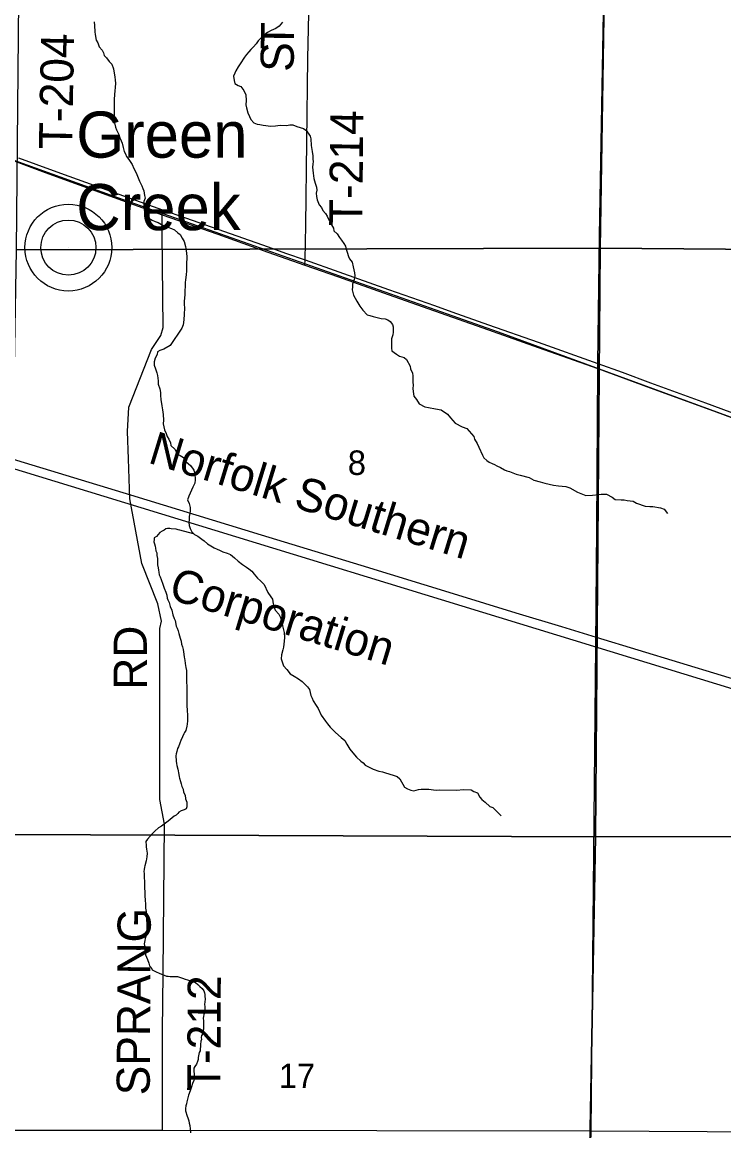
# Model space of a CAD drawing. Extents: x 36.7 to 70.7, y 0 to 22.
# Drawn here: x 42.275 to 43.478, y 17.404 to 19.304 of the extents above; entities that cross this region are included whole.
import ezdxf

# ---------------------------------------------------------------- set-up
doc = ezdxf.new("R2010")
doc.units = 0
for name, color, linetype in [('GM_X_County_Road', 7, 'Continuous'), ('GM_X_Minor_River', 7, 'Continuous'), ('GM_X_Rail_Line', 7, 'Continuous'), ('GM_X_Rail_Line_Text', 7, 'Continuous'), ('GM_X_Section', 7, 'Continuous'), ('GM_X_Section_Text', 7, 'Continuous'), ('GM_X_Township_Road', 7, 'Continuous'), ('GM_X_Township_Road_Text', 7, 'Continuous'), ('GM_X_Unincorporated', 7, 'Continuous'), ('GM_X_Unincorporated_Location', 7, 'Continuous'), ('GM_X_Unincorporated_Text', 7, 'Continuous'), ('GM_X_US_Route', 7, 'Continuous')]:
    doc.layers.add(name, color=color, linetype=linetype)

msp = doc.modelspace()

# ---------------------------------------------------------------- linework, layer by layer
at = {"layer": 'GM_X_County_Road'}
for points in [[(42.1609, 17.4056), (42.5156, 17.4053), (43.2502, 17.4045)], [(43.2502, 17.4045), (43.7467, 17.4014), (44.216, 17.4059), (44.498, 17.4024)]]:
    msp.add_lwpolyline(points, dxfattribs=at)
at = {"layer": 'GM_X_Minor_River'}
for points in [[(42.3988, 19.3045), (42.3991, 19.2985), (42.4001, 19.2871), (42.4005, 19.2829), (42.4023, 19.273), (42.4049, 19.2684), (42.4074, 19.2619), (42.4123, 19.2558), (42.4149, 19.2512), (42.4156, 19.247), (42.4197, 19.2428), (42.4242, 19.2367), (42.4291, 19.2321), (42.4317, 19.2241), (42.4331, 19.2165), (42.4342, 19.2104), (42.4349, 19.2047), (42.4352, 19.1994), (42.4347, 19.1918)], [(42.7216, 19.3041), (42.7155, 19.297), (42.7101, 19.2932), (42.7021, 19.2895), (42.696, 19.2862), (42.6907, 19.282), (42.6864, 19.2787), (42.6799, 19.2719), (42.6761, 19.2666), (42.6718, 19.2614), (42.6672, 19.2572), (42.6638, 19.2531), (42.6599, 19.2486), (42.6565, 19.2441), (42.6491, 19.2328), (42.6453, 19.2275), (42.6414, 19.2207), (42.6398, 19.2165), (42.6375, 19.2116), (42.6389, 19.204), (42.64, 19.1991), (42.6457, 19.1956), (42.6502, 19.1937), (42.6554, 19.1868), (42.6588, 19.1795), (42.6594, 19.17), (42.6589, 19.1621), (42.6596, 19.1571), (42.6618, 19.1487), (42.6648, 19.1423), (42.667, 19.1373), (42.6726, 19.1312), (42.6779, 19.1292), (42.6828, 19.1284), (42.6881, 19.1272), (42.7014, 19.1259), (42.7094, 19.1262), (42.7135, 19.1269), (42.7177, 19.1273), (42.7283, 19.1271), (42.734, 19.1282), (42.7394, 19.1282), (42.7461, 19.1251), (42.7575, 19.1215), (42.7631, 19.1177), (42.7654, 19.1135), (42.7687, 19.1085), (42.7702, 19.1043), (42.7708, 19.0929), (42.7722, 19.0826), (42.7736, 19.0747), (42.7736, 19.0693), (42.7739, 19.0652), (42.7735, 19.0606), (42.773, 19.0553), (42.7734, 19.0504), (42.7741, 19.045), (42.7751, 19.0359), (42.7773, 19.0279), (42.7795, 19.0211), (42.7802, 19.0161), (42.7794, 19.0112), (42.7797, 19.0055), (42.7811, 18.9998), (42.7844, 18.9907), (42.7882, 18.9864), (42.7904, 18.9815), (42.7949, 18.9761), (42.7979, 18.9715), (42.8005, 18.9666), (42.8034, 18.9605), (42.809, 18.9509), (42.8097, 18.9464), (42.8154, 18.941), (42.8191, 18.9352), (42.8224, 18.9303), (42.8266, 18.9249), (42.8292, 18.92), (42.8306, 18.915), (42.8321, 18.9097), (42.8343, 18.9024), (42.8361, 18.8982), (42.8406, 18.8925), (42.8428, 18.8845), (42.8449, 18.8746), (42.8456, 18.8693), (42.8441, 18.8632), (42.8413, 18.8553), (42.8413, 18.8504), (42.8408, 18.8454), (42.843, 18.8363), (42.8489, 18.826), (42.8542, 18.8172), (42.859, 18.8103), (42.8665, 18.8023)], [(42.4347, 19.1918), (42.4339, 19.1861), (42.4338, 19.18), (42.433, 19.1717), (42.4332, 19.1588), (42.433, 19.1391), (42.4336, 19.1315), (42.4351, 19.1242), (42.4369, 19.1193), (42.441, 19.1113), (42.4428, 19.1059), (42.4451, 19.1006), (42.4465, 19.0964), (42.4483, 19.0892), (42.4502, 19.0823), (42.4524, 19.0781), (42.4542, 19.0739), (42.4583, 19.0686), (42.4636, 19.0598), (42.4669, 19.0533), (42.4699, 19.0472), (42.4717, 19.043), (42.4743, 19.0373), (42.4765, 19.0315), (42.4806, 19.0235), (42.4824, 19.019), (42.4839, 19.0148), (42.4849, 19.0068), (42.486, 19.0026), (42.4841, 18.9969), (42.4836, 18.989), (42.4847, 18.9817), (42.4854, 18.9772), (42.4883, 18.9718), (42.4925, 18.9684), (42.4981, 18.9645), (42.503, 18.9622), (42.5083, 18.9606), (42.514, 18.9575), (42.5204, 18.9536), (42.5249, 18.9528), (42.5313, 18.9505), (42.5366, 18.9482), (42.5419, 18.9428), (42.546, 18.9401), (42.5494, 18.934), (42.5527, 18.9279), (42.5553, 18.9195), (42.5563, 18.9126), (42.5573, 18.9024), (42.5573, 18.8982), (42.5569, 18.8921), (42.5567, 18.8781), (42.5562, 18.8709), (42.5554, 18.8625), (42.5549, 18.858), (42.5545, 18.8504), (42.554, 18.8447), (42.5539, 18.8371), (42.5535, 18.8311), (42.5531, 18.8257), (42.553, 18.8208), (42.5533, 18.814), (42.5532, 18.8034), (42.5523, 18.7939), (42.5511, 18.7852), (42.5491, 18.7799)], [(42.8665, 18.8023), (42.871, 18.8011), (42.8767, 18.7999), (42.8813, 18.7983), (42.8858, 18.7971), (42.8903, 18.7963), (42.8972, 18.7959), (42.9021, 18.7939), (42.9062, 18.7908), (42.9099, 18.7859), (42.9114, 18.7817), (42.9109, 18.7726), (42.9105, 18.7684), (42.9085, 18.7616), (42.9083, 18.7456), (42.9087, 18.7411), (42.9169, 18.7349), (42.9222, 18.7318), (42.9298, 18.7295), (42.9339, 18.726), (42.9402, 18.7145), (42.9406, 18.71), (42.9443, 18.7024), (42.9446, 18.6978), (42.9448, 18.6872), (42.9452, 18.6818), (42.9451, 18.6765), (42.9454, 18.6712), (42.9468, 18.6632), (42.9513, 18.6575), (42.9558, 18.6498), (42.9656, 18.6448), (42.9717, 18.644), (42.9838, 18.6416), (42.9932, 18.6396), (43.0045, 18.6322), (43.0094, 18.6261), (43.0176, 18.6169), (43.0293, 18.6107), (43.0373, 18.6076), (43.0492, 18.5938), (43.0503, 18.5892), (43.0548, 18.582), (43.0581, 18.5759), (43.0644, 18.5618), (43.0666, 18.5576), (43.0715, 18.553), (43.0757, 18.5503), (43.0806, 18.5479), (43.0847, 18.546), (43.0889, 18.544), (43.0953, 18.5409), (43.1017, 18.5371), (43.1058, 18.5355), (43.1104, 18.5339), (43.1221, 18.5293), (43.1285, 18.528), (43.144, 18.5237), (43.1519, 18.5194), (43.1633, 18.5163), (43.1708, 18.5143), (43.186, 18.5107), (43.1943, 18.5095), (43.2068, 18.5086), (43.2136, 18.5059), (43.2272, 18.4989), (43.2415, 18.4931), (43.2529, 18.4933), (43.2636, 18.4947), (43.2677, 18.4954), (43.2765, 18.4953), (43.2866, 18.4903), (43.2915, 18.4861), (43.3021, 18.4856), (43.3071, 18.4855), (43.3124, 18.4843), (43.3226, 18.4834), (43.3283, 18.48), (43.343, 18.4749), (43.351, 18.4744), (43.3563, 18.4744), (43.3695, 18.4716), (43.3756, 18.4696), (43.3815, 18.4619)], [(42.5491, 18.7799), (42.5287, 18.7497), (42.518, 18.7438), (42.5115, 18.7412), (42.5073, 18.7393), (42.5065, 18.7348), (42.503, 18.7284), (42.5018, 18.7219), (42.5017, 18.7162), (42.5039, 18.7101), (42.5061, 18.7029), (42.5072, 18.6987), (42.5083, 18.6892), (42.5086, 18.6835), (42.5111, 18.6755), (42.5122, 18.6694), (42.5125, 18.6641), (42.5132, 18.6576), (42.5146, 18.6466), (42.516, 18.6398), (42.5171, 18.6318), (42.5173, 18.6219), (42.5169, 18.6159), (42.518, 18.6109), (42.519, 18.6052), (42.5224, 18.5991), (42.5239, 18.5941), (42.5265, 18.5896), (42.5298, 18.5831), (42.5301, 18.5785), (42.5369, 18.5724), (42.5417, 18.564), (42.5462, 18.5613), (42.5519, 18.5582), (42.556, 18.5513), (42.5646, 18.544), (42.5695, 18.5363), (42.5713, 18.5314), (42.5719, 18.5196), (42.5711, 18.5139), (42.5676, 18.5075), (42.561, 18.492), (42.5586, 18.4856), (42.5616, 18.4795), (42.563, 18.4723), (42.563, 18.4669), (42.5626, 18.462), (42.5617, 18.4571), (42.5613, 18.4518), (42.5612, 18.4465), (42.5616, 18.4415), (42.5634, 18.4362), (42.566, 18.4309), (42.5705, 18.4259), (42.5765, 18.4231), (42.5833, 18.4181), (42.5874, 18.4151), (42.5927, 18.4104), (42.5987, 18.4066), (42.6044, 18.4035), (42.6093, 18.4012), (42.6134, 18.3992), (42.6195, 18.3965), (42.6266, 18.3941), (42.6323, 18.3918), (42.6394, 18.3864), (42.6455, 18.3807), (42.653, 18.3745), (42.6597, 18.3703), (42.6639, 18.3676), (42.6688, 18.3633), (42.6729, 18.358), (42.6785, 18.3515), (42.6838, 18.3465), (42.6901, 18.3403), (42.6964, 18.3266), (42.7013, 18.3193), (42.7043, 18.3151), (42.7053, 18.3075), (42.7068, 18.3026), (42.709, 18.2965), (42.7153, 18.2899), (42.7183, 18.2838), (42.7201, 18.2774), (42.7216, 18.2694), (42.7241, 18.2583), (42.7248, 18.2496), (42.7243, 18.2432), (42.723, 18.2329), (42.7219, 18.2288), (42.7199, 18.2201), (42.7194, 18.2129), (42.7231, 18.201), (42.7287, 18.1949), (42.7347, 18.1876), (42.7414, 18.1834), (42.749, 18.1791), (42.755, 18.1745), (42.7644, 18.1653), (42.7677, 18.1607), (42.7703, 18.1504)], [(42.5692, 18.4273), (42.5455, 18.4336), (42.5429, 18.4344), (42.5391, 18.4352), (42.5308, 18.4361), (42.5282, 18.4366), (42.5244, 18.4366), (42.5217, 18.4359), (42.5186, 18.4333), (42.5152, 18.4319), (42.5113, 18.4293), (42.5086, 18.4263), (42.5055, 18.423), (42.5017, 18.4204), (42.5013, 18.4178), (42.5012, 18.4136), (42.5022, 18.4101), (42.5033, 18.4063), (42.504, 18.4025), (42.5046, 18.398), (42.5061, 18.3949), (42.5064, 18.39), (42.507, 18.385), (42.507, 18.3824), (42.5072, 18.377), (42.5075, 18.374), (42.5082, 18.3691), (42.5089, 18.3649), (42.5096, 18.3614), (42.5102, 18.3573), (42.5117, 18.3538), (42.5135, 18.3492), (42.5163, 18.3408), (42.5185, 18.3343), (42.5213, 18.3271), (42.5231, 18.3221), (42.5241, 18.3168), (42.5252, 18.3141), (42.5274, 18.3095), (42.5292, 18.303), (42.5317, 18.2965), (42.5334, 18.2885), (42.5359, 18.2824), (42.5374, 18.2786), (42.5394, 18.2691), (42.5409, 18.2656), (42.5427, 18.261), (42.5437, 18.2565), (42.5451, 18.2523), (42.5462, 18.2484), (42.5476, 18.2435), (42.5486, 18.2385), (42.55, 18.2336), (42.5511, 18.229), (42.5518, 18.2252), (42.5531, 18.2168), (42.5534, 18.2134), (42.5541, 18.2107), (42.5548, 18.2054), (42.5561, 18.1982), (42.5572, 18.1932), (42.5569, 18.1803), (42.5571, 18.1724), (42.5574, 18.167), (42.5573, 18.1617), (42.5575, 18.1572), (42.5578, 18.1496), (42.5576, 18.1443), (42.5578, 18.134), (42.5577, 18.1302), (42.5581, 18.1276), (42.5585, 18.1139), (42.5585, 18.1105), (42.5588, 18.1067), (42.5583, 18.1014), (42.5578, 18.0976), (42.5558, 18.0901), (42.5534, 18.0871), (42.5522, 18.0845), (42.5502, 18.0792), (42.5471, 18.0732), (42.5455, 18.0687), (42.5431, 18.0626), (42.5415, 18.0593), (42.5402, 18.0544), (42.539, 18.0502), (42.5386, 18.0472), (42.5389, 18.0438), (42.5392, 18.0411), (42.5395, 18.0377), (42.5398, 18.0339), (42.5405, 18.0301), (42.5419, 18.024), (42.5436, 18.0152), (42.5446, 18.011), (42.545, 18.0084), (42.5467, 18.003), (42.5478, 17.9988), (42.5488, 17.9943), (42.551, 17.99), (42.552, 17.9847)], [(42.7703, 18.1504), (42.7725, 18.1459), (42.7743, 18.1409), (42.7792, 18.1329), (42.7825, 18.1283), (42.7877, 18.1165), (42.7952, 18.1065), (42.7985, 18.1015), (42.803, 18.0958), (42.8124, 18.087), (42.8218, 18.0785), (42.8282, 18.0731), (42.8319, 18.067), (42.8367, 18.0582), (42.842, 18.0521), (42.8483, 18.0448), (42.8555, 18.0379), (42.8596, 18.0352), (42.863, 18.031), (42.8713, 18.0268), (42.8769, 18.024), (42.8868, 18.0209), (42.8928, 18.0197), (42.8981, 18.0177), (42.9113, 18.0138), (42.9178, 18.0118), (42.9223, 18.0076), (42.9304, 17.9935), (42.9357, 17.9904), (42.9414, 17.988), (42.9463, 17.9869), (42.9547, 17.989), (42.9589, 17.9898), (42.968, 17.9897), (42.9721, 17.99), (42.9805, 17.9888), (42.985, 17.9883), (42.9911, 17.9887), (43.0191, 17.9883), (43.0324, 17.9893), (43.0446, 17.9885), (43.0495, 17.9857), (43.0559, 17.9834), (43.0596, 17.9761), (43.0633, 17.9719), (43.0686, 17.9673), (43.0765, 17.9604), (43.0822, 17.9584), (43.0919, 17.9485), (43.0964, 17.9442)], [(42.552, 17.9847), (42.5546, 17.9793), (42.5552, 17.9733), (42.5563, 17.9706), (42.5574, 17.9675), (42.5573, 17.9641), (42.5576, 17.9596), (42.5564, 17.9562), (42.5529, 17.9544), (42.5476, 17.9529), (42.5438, 17.9507), (42.5422, 17.9481), (42.5395, 17.9455), (42.536, 17.9433), (42.5253, 17.9352), (42.5187, 17.9296), (42.5141, 17.9263), (42.5087, 17.9234), (42.5029, 17.9178), (42.4991, 17.9145), (42.4902, 17.9044), (42.4874, 17.8999), (42.4877, 17.8934), (42.488, 17.8908), (42.4887, 17.887), (42.4893, 17.8801), (42.4892, 17.8737), (42.4887, 17.8703), (42.4879, 17.8669), (42.4858, 17.8586), (42.485, 17.8559), (42.4842, 17.8522), (42.4841, 17.8488), (42.4844, 17.8453), (42.4846, 17.8385), (42.4852, 17.8317), (42.485, 17.8222), (42.4856, 17.8123), (42.4854, 17.8051), (42.4861, 17.8013), (42.4867, 17.7911), (42.4869, 17.7861), (42.4876, 17.7804), (42.4882, 17.7747), (42.4885, 17.7694), (42.4884, 17.7648), (42.4891, 17.7603), (42.4888, 17.7478), (42.4879, 17.7398), (42.4874, 17.7372), (42.4862, 17.7338), (42.4854, 17.7304), (42.4845, 17.7251), (42.4849, 17.7221), (42.4848, 17.7183), (42.4855, 17.7156), (42.4858, 17.7122), (42.4865, 17.7088), (42.4868, 17.7057), (42.4882, 17.7019), (42.49, 17.6981), (42.4922, 17.6919), (42.4936, 17.687), (42.4962, 17.6843), (42.498, 17.6805), (42.5006, 17.6789), (42.504, 17.6777), (42.5115, 17.6741), (42.516, 17.6721), (42.5186, 17.6713), (42.5228, 17.6697), (42.5258, 17.6693), (42.5292, 17.6688), (42.5322, 17.6688), (42.5352, 17.6691), (42.5417, 17.669), (42.5469, 17.6673), (42.5499, 17.6658), (42.5544, 17.6645), (42.5586, 17.6633), (42.5623, 17.6621), (42.5725, 17.6585), (42.5762, 17.655), (42.5799, 17.6515), (42.5836, 17.6484), (42.5866, 17.6442), (42.588, 17.6411), (42.5883, 17.6381), (42.5886, 17.6339), (42.589, 17.6312), (42.5881, 17.6244), (42.588, 17.6218), (42.5883, 17.6164), (42.5882, 17.6134), (42.5878, 17.61), (42.5877, 17.607), (42.5869, 17.6036), (42.586, 17.6006), (42.5856, 17.5972), (42.5859, 17.593), (42.5862, 17.5899)], [(42.5862, 17.5899), (42.586, 17.5805), (42.5847, 17.5706), (42.5827, 17.5676), (42.5823, 17.5642), (42.5826, 17.5608), (42.5818, 17.5582), (42.5809, 17.5525), (42.5806, 17.5415), (42.5787, 17.5389), (42.5774, 17.5328), (42.577, 17.5298), (42.5769, 17.5268), (42.5761, 17.5234), (42.5741, 17.5189), (42.571, 17.5148), (42.5694, 17.5118), (42.5694, 17.5087), (42.5697, 17.5053), (42.57, 17.5026), (42.5702, 17.4966), (42.5702, 17.4932), (42.5694, 17.4905), (42.5674, 17.4856), (42.5657, 17.4796), (42.5633, 17.4728), (42.5605, 17.4653), (42.5576, 17.4543), (42.5568, 17.4509), (42.556, 17.4472), (42.5551, 17.4426), (42.5554, 17.4388), (42.5583, 17.4297), (42.5593, 17.4266), (42.5607, 17.4217), (42.5618, 17.4178), (42.5625, 17.4133), (42.5631, 17.4076), (42.5637, 17.4011)]]:
    msp.add_lwpolyline(points, dxfattribs=at)
at = {"layer": 'GM_X_Rail_Line'}
for points in [[(39.9505, 19.9142), (40.2796, 19.7934), (40.742, 19.6245), (41.298, 19.4193), (41.8828, 19.2032), (42.4402, 19.0032), (43.0913, 18.7734), (43.6618, 18.5644), (44.5563, 18.22), (44.9526, 18.0665), (45.405, 17.9057), (45.5934, 17.8393)], [(39.4351, 19.5275), (39.5072, 19.4857), (39.6526, 19.4084), (39.8435, 19.3143), (39.9823, 19.2538), (40.1053, 19.2054), (40.2394, 19.1588), (40.707, 19.0117), (41.5752, 18.749), (42.4154, 18.492), (43.2547, 18.2349), (44.5058, 17.8517), (44.9515, 17.7199), (45.506, 17.5551), (45.5934, 17.5283)], [(42.2523, 18.5576), (42.4612, 18.4939), (42.6848, 18.4257), (42.8556, 18.3736), (43.0138, 18.3251), (43.1215, 18.2922), (43.1997, 18.2684), (43.259, 18.2503), (43.7587, 18.0984)]]:
    msp.add_lwpolyline(points, dxfattribs=at)
at = {"layer": 'GM_X_Section'}
for points in [[(44.2753, 19.8692), (44.2682, 18.9088), (43.2658, 18.9165), (43.2807, 19.8534), (43.3171, 19.855)], [(43.2807, 19.8534), (43.2658, 18.9165), (42.2659, 18.914), (42.2743, 19.8312), (42.3088, 19.8313)], [(43.2658, 18.9165), (43.2576, 17.9081), (42.2487, 17.912), (42.2659, 18.914)], [(44.2682, 18.9088), (44.2567, 17.9094), (43.2576, 17.9081), (43.2658, 18.9165)], [(43.2576, 17.9081), (43.2397, 16.908), (42.2388, 16.9146), (42.2487, 17.912)], [(44.2567, 17.9094), (44.2493, 16.9097), (43.2397, 16.908), (43.2576, 17.9081)]]:
    msp.add_lwpolyline(points, close=True, dxfattribs=at)
at = {"layer": 'GM_X_Township_Road'}
for p, q in [((43.2502, 17.4045), (43.2582, 18.2354)), ((43.2265, 16.2915), (43.2502, 17.4045))]:
    msp.add_line(p, q, dxfattribs=at)
for points in [[(42.76, 18.8877), (42.7602, 18.8965), (42.7612, 18.9559), (42.765, 19.2416), (42.7688, 19.4225)], [(43.2619, 18.7104), (43.262, 18.7192), (43.2645, 18.9386), (43.2731, 19.4156)], [(42.5153, 18.9641), (42.5155, 18.9741), (42.5157, 18.9826)], [(42.4601, 18.4872), (42.4574, 18.5556), (42.4559, 18.6027), (42.4581, 18.6444), (42.4969, 18.7433), (42.5128, 18.767), (42.5169, 18.7806), (42.515, 18.9412), (42.5153, 18.9641)], [(43.2582, 18.2354), (43.2601, 18.4382), (43.2619, 18.7104)], [(42.5169, 17.6753), (42.5191, 17.9298), (42.511, 17.9724), (42.5112, 18.2653), (42.5144, 18.2778), (42.5077, 18.3075), (42.4807, 18.3763), (42.4601, 18.4872)], [(42.5156, 17.4053), (42.516, 17.5758), (42.5169, 17.6733), (42.5169, 17.6753)]]:
    msp.add_lwpolyline(points, dxfattribs=at)
at = {"layer": 'GM_X_Unincorporated'}
for radius in [0.0744, 0.0472]:
    msp.add_circle((42.3545, 18.9177), radius, dxfattribs=at)
at = {"layer": 'GM_X_Unincorporated_Location'}
msp.add_line((42.3545, 18.9177), (42.3545, 18.9177), dxfattribs=at)
at = {"layer": 'GM_X_US_Route'}
for points in [[(42.0511, 19.1417), (42.0769, 19.1324), (42.212, 19.0834), (42.2689, 19.0633), (42.3145, 19.0466)], [(42.2689, 19.0716), (42.2986, 19.0608), (42.3411, 19.0455), (42.4267, 19.0145), (42.4694, 18.999), (42.5157, 18.9826), (42.555, 18.9687), (42.6107, 18.9493), (42.6967, 18.9188), (42.7264, 18.9082), (42.7602, 18.8965)], [(42.3145, 19.0466), (42.3401, 19.0373), (42.4329, 19.0037), (42.5155, 18.9741), (42.6105, 18.9405), (42.6966, 18.9101), (42.76, 18.8877)], [(42.76, 18.8877), (42.8177, 18.8674), (42.9028, 18.8372), (42.9817, 18.8095), (43.0744, 18.7767), (43.1596, 18.7467), (43.2619, 18.7104)], [(42.7602, 18.8965), (42.8178, 18.8762), (42.9029, 18.8461), (42.9818, 18.8183), (43.0116, 18.8076), (43.0745, 18.7855), (43.1598, 18.7556), (43.262, 18.7192)], [(43.2619, 18.7104), (43.3516, 18.6776), (43.4647, 18.6361), (43.5573, 18.6019), (43.6494, 18.5681), (43.7274, 18.5394), (43.7627, 18.5265), (43.784, 18.5188), (43.8265, 18.503), (43.8696, 18.4872), (43.9118, 18.4714), (43.9545, 18.4552), (43.9835, 18.444), (44.0037, 18.4362), (44.0806, 18.4058), (44.1723, 18.3695), (44.2709, 18.3302), (44.355, 18.297), (44.4462, 18.2608), (44.4681, 18.2519)], [(43.262, 18.7192), (43.3034, 18.7041), (43.3522, 18.6861), (43.4462, 18.6516), (43.4883, 18.6361), (43.5456, 18.6151), (43.5947, 18.597), (43.6501, 18.5766), (43.7293, 18.5476), (43.7633, 18.535), (43.7861, 18.5267), (43.8268, 18.5118), (43.8699, 18.4959), (43.9134, 18.4799), (43.9561, 18.4638), (43.9846, 18.4527), (44.004, 18.445), (44.0406, 18.4305), (44.0821, 18.4139), (44.1738, 18.3777), (44.2724, 18.3384), (44.3565, 18.3051), (44.4477, 18.2689), (44.4696, 18.2601)]]:
    msp.add_lwpolyline(points, dxfattribs=at)

# ---------------------------------------------------------------- texts
at = {"layer": 'GM_X_Rail_Line_Text'}
for s, rotation, p in [('Norfolk Southern', 342.9781, (42.4892, 18.5496)), ('Corporation', 343.0149, (42.5241, 18.3167))]:
    msp.add_text(s, height=0.056629, rotation=rotation, dxfattribs=at).set_placement(p)
at = {"layer": 'GM_X_Section_Text'}
for s, height, p in [('8', 0.0419, (42.8334, 18.5282)), ('17', 0.04186, (42.7151, 17.4778))]:
    msp.add_text(s, height=height, rotation=0, dxfattribs=at).set_placement(p)
at = {"layer": 'GM_X_Township_Road_Text'}
for s, height, rotation, p in [('T', 0.0568, 89.4257, (42.741, 19.2571)), ('T-204', 0.05682, 88.8762, (42.3607, 19.0857)), ('S', 0.0568, 89.4251, (42.7406, 19.2187)), ('T-214', 0.05682, 89.4386, (42.8582, 18.9542)), ('RD', 0.05682, 90, (42.489, 18.1602)), ('SPRANG', 0.05682, 89.6516, (42.4939, 17.4652)), ('T-212', 0.05682, 89.7193, (42.6149, 17.4722))]:
    msp.add_text(s, height=height, rotation=rotation, dxfattribs=at).set_placement(p)
at = {"layer": 'GM_X_Unincorporated_Text'}
for s, p in [('Green', (42.368, 19.0718)), ('Creek', (42.368, 18.9476))]:
    msp.add_text(s, height=0.07898, rotation=0, dxfattribs=at).set_placement(p)

doc.saveas('drawing.dxf')
